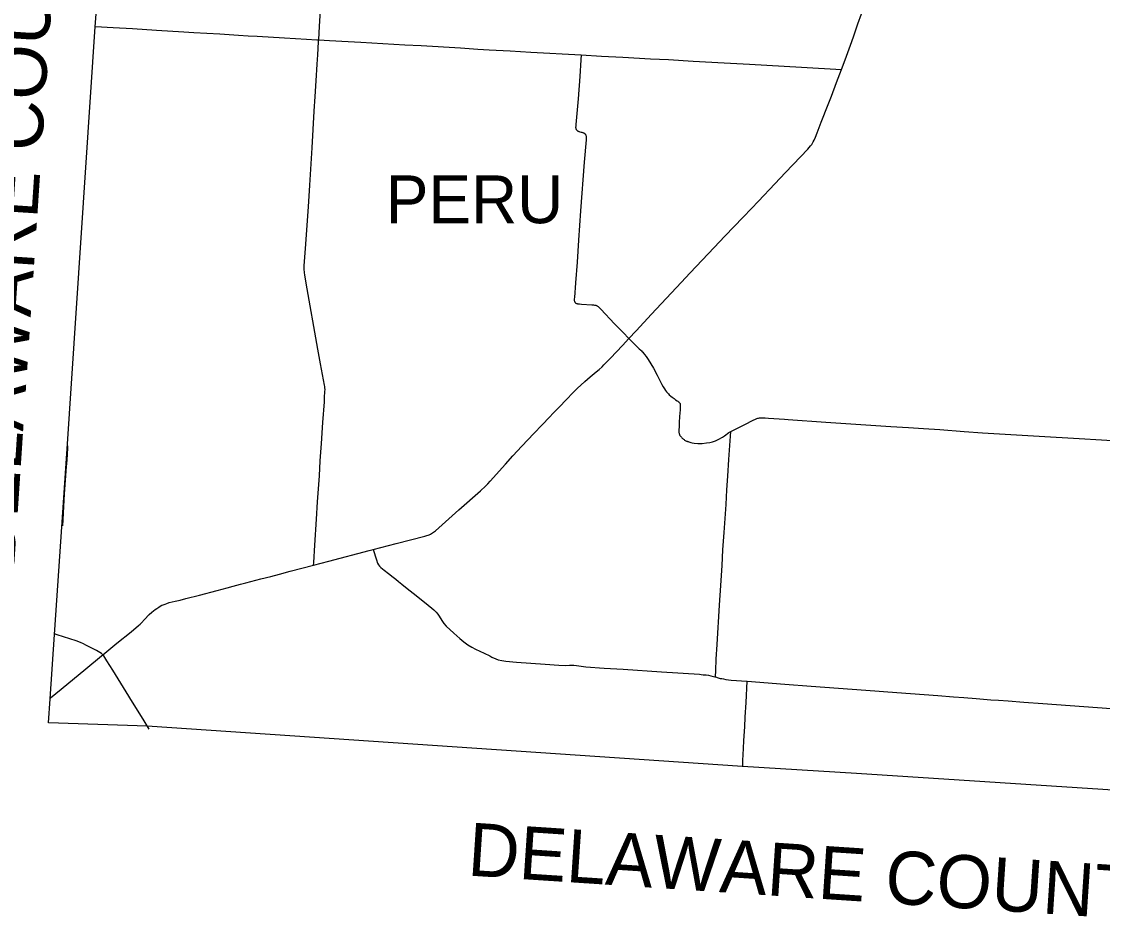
# Model space of a CAD drawing. Extents: x 9078 to 9739, y 4248 to 4966.
# Drawn here: x 9241.2 to 9343, y 4277 to 4361.8 of the extents above; entities that cross this region are included whole.
import ezdxf

# ---------------------------------------------------------------- set-up
doc = ezdxf.new("R2010")
doc.units = 0
for name, color, linetype in [('GM_X_Adjacent_County_Text', 7, 'Continuous'), ('GM_X_County', 7, 'Continuous'), ('GM_X_County_Road', 7, 'Continuous'), ('GM_X_Township_Road', 7, 'Continuous'), ('GM_X_Township_Text', 7, 'Continuous')]:
    doc.layers.add(name, color=color, linetype=linetype)

msp = doc.modelspace()

# ---------------------------------------------------------------- linework, layer by layer
at = {"layer": 'GM_X_County'}
msp.add_lwpolyline([(9453.47, 4282.4), (9434.47, 4283.67), (9411.76, 4284.99), (9398.2, 4285.94), (9380.71, 4287.14), (9368.35, 4287.79), (9345.5, 4289.28), (9319.89, 4290.94), (9309.14, 4291.62), (9253.07, 4295.4), (9243.76, 4295.73), (9243.93, 4298), (9244.32, 4304.05), (9245.53, 4321.55), (9248.17, 4361.29), (9250.08, 4386.45), (9250.73, 4399.27), (9229.79, 4400.68)], dxfattribs=at)
at = {"layer": 'GM_X_County_Road'}
for points in [[(9269.22, 4360.07), (9269.3, 4361.37), (9269.5, 4364.89), (9269.59, 4366.37), (9269.74, 4368.65), (9269.82, 4369.89), (9269.97, 4372.18), (9270.06, 4373.41), (9270.13, 4374.39), (9270.19, 4375.37), (9270.42, 4378.81), (9270.55, 4380.78), (9270.85, 4385.45)], [(9318.48, 4357.29), (9318.82, 4358.2), (9319.07, 4358.9), (9319.32, 4359.59), (9319.59, 4360.36), (9320.02, 4361.6), (9320.36, 4362.53), (9320.42, 4362.71)], [(9268.74, 4310.59), (9268.75, 4310.83), (9268.85, 4312.46), (9269.01, 4314.92), (9269.11, 4316.56), (9269.28, 4319.01), (9269.37, 4320.41), (9269.47, 4322.04), (9269.61, 4324.01), (9269.75, 4325.97), (9269.77, 4326.37), (9269.8, 4326.96), (9269.81, 4327.13), (9269.8, 4327.29), (9269.79, 4327.41), (9269.77, 4327.53), (9269.4, 4329.55), (9269.15, 4330.92), (9268.04, 4337.14), (9267.9, 4337.95), (9267.88, 4338.14), (9267.87, 4338.26), (9267.86, 4338.37), (9267.86, 4338.51), (9267.86, 4338.77), (9267.97, 4340.41), (9268.24, 4344.34), (9268.37, 4346.38), (9268.59, 4349.91), (9268.8, 4353.35), (9268.89, 4354.74), (9268.99, 4356.21), (9269.08, 4357.77), (9269.14, 4358.67), (9269.21, 4359.9), (9269.22, 4360.07)], [(9298.43, 4331.94), (9299.12, 4332.67), (9299.84, 4333.46), (9300.58, 4334.23), (9303.37, 4337.23), (9304.22, 4338.12), (9306.47, 4340.51), (9307.49, 4341.58), (9309.19, 4343.36), (9309.98, 4344.19), (9310.66, 4344.89), (9312.19, 4346.5), (9313.2, 4347.57), (9314.61, 4349.06), (9315.3, 4349.77), (9315.56, 4350.08), (9315.66, 4350.21), (9315.74, 4350.35), (9315.8, 4350.46), (9315.88, 4350.61), (9316.01, 4350.91), (9316.18, 4351.32), (9316.56, 4352.31), (9317.21, 4353.99), (9317.51, 4354.76), (9318.01, 4356.06), (9318.48, 4357.29)], [(9274.35, 4312.05), (9276.51, 4312.61), (9279.21, 4313.31), (9279.4, 4313.37), (9279.52, 4313.41), (9279.61, 4313.45), (9279.74, 4313.51), (9279.95, 4313.64), (9280.21, 4313.83), (9282.42, 4315.79), (9284.45, 4317.58), (9284.93, 4318.03), (9285.16, 4318.26), (9285.38, 4318.5), (9286.81, 4320.09), (9287.52, 4320.87), (9288.34, 4321.79), (9289.48, 4322.98), (9290.27, 4323.81), (9290.95, 4324.52), (9291.31, 4324.9), (9291.9, 4325.51), (9292.54, 4326.17), (9292.72, 4326.36), (9292.99, 4326.65), (9293.58, 4327.22), (9294.3, 4327.88), (9294.8, 4328.32), (9295.37, 4328.79), (9295.63, 4329.02), (9295.91, 4329.27), (9296.09, 4329.45), (9296.27, 4329.64), (9296.71, 4330.1), (9297.83, 4331.29), (9298.43, 4331.94)], [(9298.43, 4331.94), (9298.5, 4331.87), (9298.57, 4331.8), (9299, 4331.36), (9299.41, 4330.98), (9299.55, 4330.85), (9299.63, 4330.77), (9299.7, 4330.69), (9299.75, 4330.64), (9299.81, 4330.56), (9299.92, 4330.43), (9300.05, 4330.25), (9300.24, 4329.97), (9300.75, 4329.13), (9301.1, 4328.48), (9301.55, 4327.61), (9301.68, 4327.39), (9301.8, 4327.19), (9301.9, 4327.04), (9301.98, 4326.92), (9302.07, 4326.81), (9302.16, 4326.72), (9302.24, 4326.63), (9302.39, 4326.51), (9302.51, 4326.41), (9302.69, 4326.28), (9302.84, 4326.17), (9302.98, 4326.08), (9303.04, 4326.03), (9303.09, 4326), (9303.11, 4325.98), (9303.12, 4325.97), (9303.13, 4325.96), (9303.15, 4325.95), (9303.17, 4325.92), (9303.21, 4325.88), (9303.23, 4325.86), (9303.24, 4325.84), (9303.25, 4325.83), (9303.26, 4325.81), (9303.27, 4325.78), (9303.27, 4325.77), (9303.28, 4325.76), (9303.28, 4325.74), (9303.28, 4325.73), (9303.28, 4325.57), (9303.27, 4325.46), (9303.26, 4325.22), (9303.22, 4324.59), (9303.18, 4324.01), (9303.16, 4323.65), (9303.14, 4323.3), (9303.14, 4323.23), (9303.14, 4323.17), (9303.14, 4323.12), (9303.15, 4323.07), (9303.16, 4323.02), (9303.17, 4322.98), (9303.2, 4322.9), (9303.21, 4322.86), (9303.25, 4322.81), (9303.28, 4322.76), (9303.33, 4322.7), (9303.38, 4322.64), (9303.43, 4322.58), (9303.49, 4322.52), (9303.56, 4322.47), (9303.59, 4322.44), (9303.63, 4322.41), (9303.68, 4322.37), (9303.74, 4322.34), (9303.81, 4322.31), (9303.86, 4322.28), (9303.92, 4322.26), (9303.97, 4322.24), (9304.03, 4322.22), (9304.08, 4322.2), (9304.28, 4322.14), (9304.39, 4322.12), (9304.6, 4322.08), (9304.92, 4322.06), (9305.33, 4322.06), (9305.74, 4322.1), (9306.06, 4322.14), (9306.3, 4322.2), (9306.61, 4322.31), (9306.91, 4322.44), (9307.26, 4322.64), (9307.46, 4322.78), (9307.85, 4323.07), (9307.93, 4323.12), (9308.03, 4323.19)], [(9308.03, 4323.19), (9308.48, 4323.4), (9308.85, 4323.58), (9309.35, 4323.85), (9310.14, 4324.26), (9310.37, 4324.35), (9310.48, 4324.39), (9310.6, 4324.42), (9310.65, 4324.44), (9310.75, 4324.45), (9310.81, 4324.46), (9310.86, 4324.46), (9310.92, 4324.46), (9311, 4324.46), (9311.12, 4324.45), (9311.28, 4324.45), (9311.59, 4324.43), (9313.1, 4324.33), (9313.43, 4324.31), (9316.98, 4324.07), (9323.1, 4323.66), (9324.79, 4323.55), (9326.19, 4323.46), (9327.73, 4323.35), (9330.02, 4323.19), (9331.76, 4323.06), (9337.09, 4322.75), (9340.87, 4322.51), (9342.97, 4322.38), (9345.41, 4322.23)], [(9306.6, 4300.06), (9306.62, 4300.66), (9306.67, 4301.73), (9306.74, 4303.12), (9306.97, 4306.8), (9307.09, 4308.68), (9307.22, 4310.56), (9307.3, 4312.03), (9307.41, 4313.67), (9307.59, 4316.29), (9307.68, 4317.68), (9307.76, 4318.98), (9307.85, 4320.54), (9308.03, 4323.19)], [(9268.74, 4310.59), (9270.16, 4310.96), (9273.97, 4311.95), (9274.35, 4312.05)], [(9274.35, 4312.05), (9274.65, 4311.08), (9274.77, 4310.77), (9274.85, 4310.62), (9274.95, 4310.49), (9275.07, 4310.37), (9275.39, 4310.11), (9275.78, 4309.81), (9276.22, 4309.45), (9276.47, 4309.25), (9276.73, 4309.05), (9277.05, 4308.8), (9277.56, 4308.4), (9278.13, 4307.93), (9279.35, 4306.96), (9280.05, 4306.39), (9280.29, 4306.17), (9280.44, 4305.98), (9280.57, 4305.78), (9280.82, 4305.36), (9281.02, 4305.09), (9281.24, 4304.85), (9281.95, 4304.17), (9282.5, 4303.67), (9282.88, 4303.36), (9283.28, 4303.08), (9283.63, 4302.86), (9284, 4302.68), (9284.81, 4302.3), (9285.33, 4302.04)], [(9248.89, 4302.15), (9249.25, 4302.45), (9250.21, 4303.23), (9251.54, 4304.31), (9252.23, 4304.89), (9252.39, 4305.03), (9252.53, 4305.16), (9252.82, 4305.46), (9253.26, 4305.94), (9253.5, 4306.16), (9253.82, 4306.41), (9253.96, 4306.51), (9254.16, 4306.64), (9254.29, 4306.72), (9254.44, 4306.8), (9254.56, 4306.85), (9254.74, 4306.92), (9254.92, 4306.98), (9255.12, 4307.05), (9255.68, 4307.19), (9256.15, 4307.3), (9256.69, 4307.44), (9257.98, 4307.77), (9259.64, 4308.21), (9260.59, 4308.46), (9261.15, 4308.61), (9261.86, 4308.79), (9262.34, 4308.91), (9263.29, 4309.16), (9263.76, 4309.29), (9264.71, 4309.53), (9265.51, 4309.75), (9266.53, 4310.02), (9268.74, 4310.59)], [(9248.89, 4302.15), (9248.77, 4302.25), (9248.6, 4302.37), (9248.45, 4302.46), (9248.28, 4302.55), (9248.04, 4302.68), (9247.35, 4303.03), (9247, 4303.19), (9246.83, 4303.27), (9246.61, 4303.35), (9246.37, 4303.44), (9244.58, 4304.03), (9244.34, 4304.11)], [(9243.94, 4298.09), (9244.95, 4298.91), (9247.29, 4300.83), (9248.74, 4302.04), (9248.89, 4302.15)], [(9253.25, 4295.13), (9252.67, 4296.08), (9251.69, 4297.68), (9251.08, 4298.65), (9249.83, 4300.68), (9249.27, 4301.56), (9248.97, 4302.03), (9248.89, 4302.15)], [(9285.33, 4302.04), (9285.53, 4301.93), (9285.9, 4301.75), (9286.13, 4301.66), (9286.46, 4301.59), (9286.86, 4301.53), (9287.85, 4301.45), (9290.54, 4301.25), (9291.85, 4301.15), (9292.43, 4301.13), (9292.84, 4301.15), (9293.24, 4301.16), (9293.49, 4301.14), (9294.38, 4301.02), (9296.1, 4300.89), (9297.9, 4300.77), (9301.5, 4300.54), (9305.1, 4300.3), (9305.26, 4300.28)], [(9305.26, 4300.28), (9305.45, 4300.26), (9305.71, 4300.24), (9305.93, 4300.21), (9306.15, 4300.17), (9306.55, 4300.07), (9306.6, 4300.06)], [(9306.6, 4300.06), (9306.86, 4299.97), (9307.04, 4299.92), (9307.18, 4299.89), (9307.34, 4299.86), (9307.58, 4299.81), (9307.82, 4299.78), (9308.07, 4299.76), (9309.55, 4299.64), (9309.58, 4299.64)], [(9309.17, 4291.57), (9309.17, 4291.76), (9309.18, 4292.17), (9309.23, 4293.31), (9309.27, 4294.05), (9309.35, 4295.36), (9309.4, 4296.26), (9309.48, 4297.65), (9309.58, 4299.64)], [(9309.58, 4299.64), (9313.14, 4299.37), (9315.6, 4299.18), (9320.75, 4298.81), (9323.69, 4298.58), (9327.54, 4298.29), (9329.01, 4298.18), (9329.99, 4298.11), (9331.14, 4298.02), (9332.53, 4297.91), (9333.26, 4297.87), (9334.16, 4297.8), (9335.63, 4297.69), (9337.43, 4297.56), (9342.58, 4297.17), (9346.84, 4296.85), (9347.12, 4296.83)]]:
    msp.add_lwpolyline(points, dxfattribs=at)
at = {"layer": 'GM_X_Township_Road'}
for points in [[(9248.2, 4361.34), (9249.84, 4361.24), (9251.67, 4361.13), (9253.94, 4360.99), (9256.5, 4360.84), (9257.46, 4360.78), (9259.89, 4360.63), (9261.65, 4360.51), (9262.56, 4360.47), (9263.41, 4360.42), (9265.98, 4360.26), (9268.06, 4360.13), (9269.05, 4360.08), (9269.22, 4360.07)], [(9269.22, 4360.07), (9270.24, 4360.01), (9271.98, 4359.92), (9273.2, 4359.85), (9277.32, 4359.62), (9278.88, 4359.53), (9282.57, 4359.31), (9284.21, 4359.21), (9285.27, 4359.15), (9287.24, 4359.04), (9289.21, 4358.93), (9293.94, 4358.65)], [(9293.94, 4358.65), (9293.92, 4358.2), (9293.81, 4356.63), (9293.65, 4354.51), (9293.47, 4352.46), (9293.44, 4352.1), (9293.43, 4352.04), (9293.43, 4351.98), (9293.43, 4351.93), (9293.43, 4351.9), (9293.42, 4351.86), (9293.42, 4351.83), (9293.43, 4351.79), (9293.43, 4351.77), (9293.44, 4351.74), (9293.45, 4351.7), (9293.46, 4351.66), (9293.48, 4351.63), (9293.5, 4351.6), (9293.52, 4351.57), (9293.55, 4351.54), (9293.58, 4351.52), (9293.61, 4351.5), (9293.64, 4351.48), (9293.67, 4351.47), (9293.69, 4351.46), (9293.73, 4351.45), (9293.75, 4351.44), (9293.82, 4351.42), (9293.94, 4351.39), (9294.01, 4351.37), (9294.06, 4351.36), (9294.08, 4351.35), (9294.11, 4351.34), (9294.13, 4351.33), (9294.18, 4351.32), (9294.19, 4351.31), (9294.21, 4351.29), (9294.23, 4351.28), (9294.25, 4351.26), (9294.28, 4351.24), (9294.29, 4351.22), (9294.31, 4351.21), (9294.32, 4351.19), (9294.34, 4351.17), (9294.36, 4351.14), (9294.37, 4351.12), (9294.38, 4351.08), (9294.39, 4351.05), (9294.4, 4351.01), (9294.41, 4350.98), (9294.41, 4350.9), (9294.41, 4350.77), (9294.4, 4350.65), (9294.23, 4348.54), (9293.89, 4343.96), (9293.78, 4342.58), (9293.69, 4341.19), (9293.55, 4339.14), (9293.4, 4337.18), (9293.3, 4335.81), (9293.29, 4335.69), (9293.28, 4335.61), (9293.28, 4335.58), (9293.29, 4335.54), (9293.29, 4335.51), (9293.3, 4335.47), (9293.31, 4335.44), (9293.32, 4335.4), (9293.33, 4335.38), (9293.34, 4335.37), (9293.37, 4335.34), (9293.39, 4335.31), (9293.42, 4335.29), (9293.45, 4335.27), (9293.49, 4335.25), (9293.52, 4335.24), (9293.56, 4335.23), (9293.59, 4335.22), (9293.64, 4335.21), (9293.67, 4335.2), (9293.7, 4335.2), (9293.77, 4335.19), (9293.96, 4335.17), (9294.94, 4335.12), (9295.1, 4335.1), (9295.2, 4335.09), (9295.25, 4335.08), (9295.32, 4335.07), (9295.35, 4335.06), (9295.39, 4335.05), (9295.44, 4335.02), (9295.49, 4334.99), (9295.53, 4334.96), (9295.57, 4334.92), (9295.61, 4334.89), (9295.81, 4334.7), (9297.09, 4333.32), (9297.9, 4332.5), (9298.43, 4331.94)], [(9293.94, 4358.65), (9295.85, 4358.54), (9297.87, 4358.43), (9300.47, 4358.3), (9302.16, 4358.21), (9304.5, 4358.08), (9307.42, 4357.92), (9309.79, 4357.79), (9314.7, 4357.5), (9318.48, 4357.29)], [(9245.1, 4314.28), (9245.28, 4317.31), (9245.45, 4319.89), (9245.51, 4320.46), (9245.58, 4321.6), (9245.58, 4321.64), (9245.59, 4321.69), (9245.59, 4321.72), (9245.58, 4321.76), (9245.58, 4321.77), (9245.58, 4321.79), (9245.57, 4321.81), (9245.56, 4321.84), (9245.55, 4321.86), (9245.54, 4321.89)]]:
    msp.add_lwpolyline(points, dxfattribs=at)

# ---------------------------------------------------------------- texts
at = {"layer": 'GM_X_Adjacent_County_Text'}
for rotation, p in [(86.2231, (9240.51, 4310.18)), (356.2231, (9283.17, 4281.35))]:
    msp.add_text('DELAWARE COUNTY', height=5, rotation=rotation, dxfattribs=at).set_placement(p)
at = {"layer": 'GM_X_Township_Text'}
msp.add_text('PERU', height=4.5, rotation=0, dxfattribs=at).set_placement((9275.54, 4342.8))

doc.saveas('drawing.dxf')
